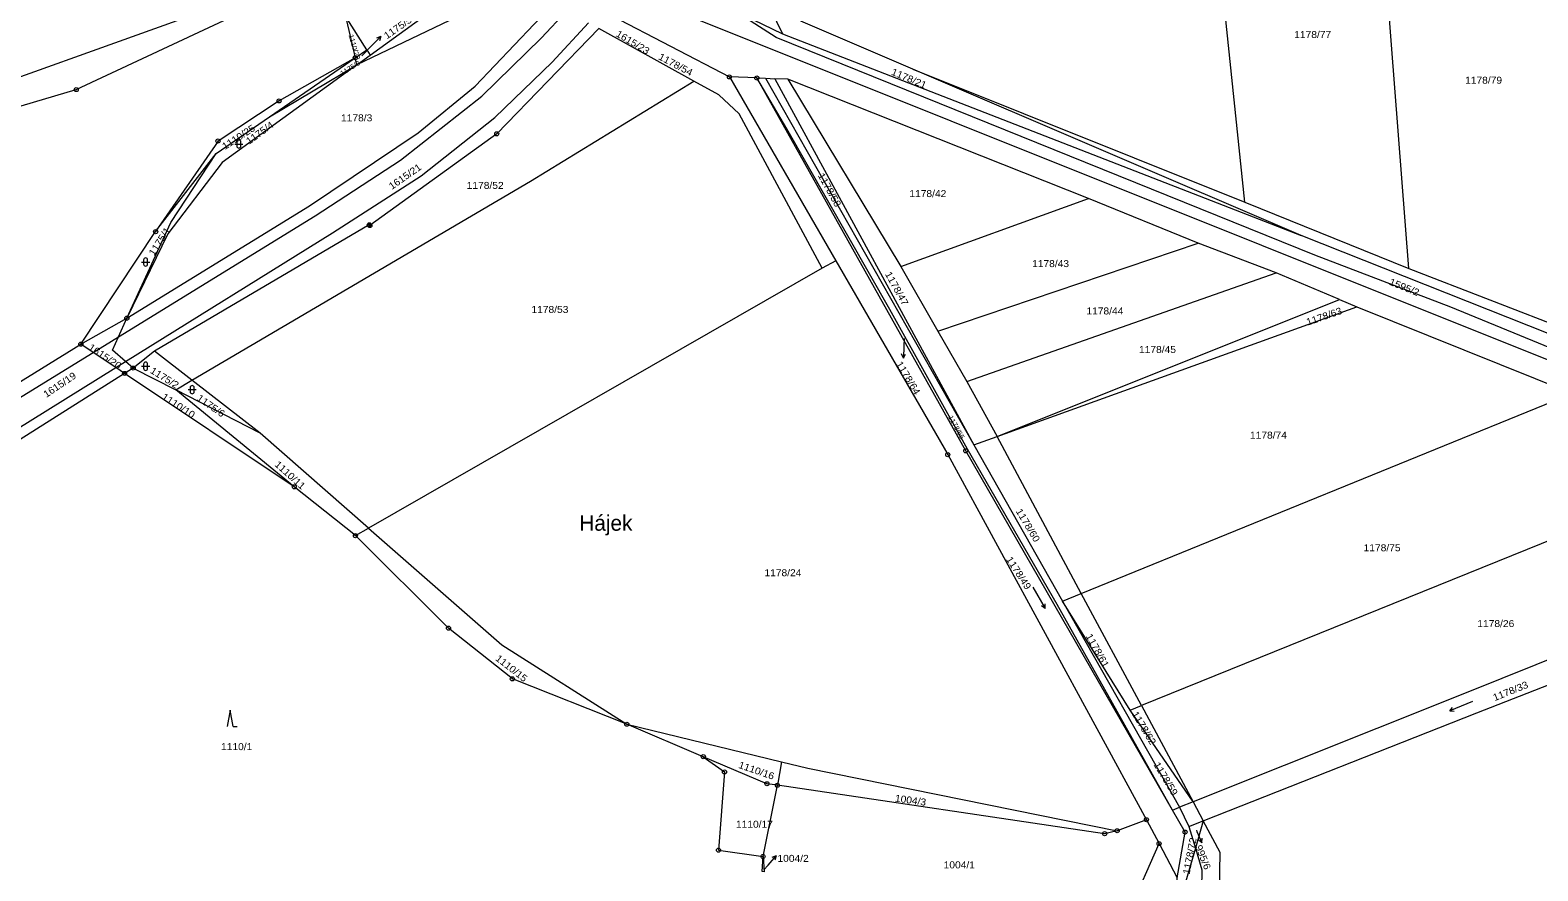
# Model space of a CAD drawing. Extents: x -686207 to -681951, y -1020493 to -1017811.
# Drawn here: x -684095.1 to -683726.8, y -1019496.1 to -1019290.6 of the extents above; entities that cross this region are included whole.
import ezdxf

# ---------------------------------------------------------------- set-up
doc = ezdxf.new("R2010")
doc.units = 0
doc.header["$LTSCALE"] = 0.4
for name, color, linetype, lineweight in [('1', 7, 'Continuous', 13), ('3', 7, 'Continuous', 13), ('4', 7, 'Continuous', 13), ('6', 7, 'Continuous', 13), ('7', 7, 'Continuous', 13), ('8', 7, 'Continuous', 13)]:
    doc.layers.add(name, color=color, linetype=linetype, lineweight=lineweight)
doc.layers.add('2', color=7, linetype='Continuous')

msp = doc.modelspace()

# ---------------------------------------------------------------- linework, layer by layer
at = {"layer": '1'}
for p, q in [((-683798.39, -1019332.66), (-683808.23, -1019238.56)), ((-683758.33, -1019348.91), (-683766.38, -1019244.39)), ((-683915.94, -1019282.08), (-683911.3, -1019291.57)), ((-684012.88, -1019295.44), (-684018.07, -1019287.22)), ((-684018.07, -1019287.22), (-684015.7, -1019297.38)), ((-683953.11, -1019287.03), (-683924.31, -1019302.07)), ((-683923.28, -1019285.78), (-683911.3, -1019291.57)), ((-683879.46, -1019300.17), (-683906.82, -1019288.43)), ((-683933.01, -1019303.08), (-683956.2, -1019290.22)), ((-683911.3, -1019291.57), (-683784.66, -1019340.83)), ((-684015.7, -1019297.38), (-684012.88, -1019295.44)), ((-684012.88, -1019295.44), (-684012.06, -1019296.74)), ((-684036.69, -1019311.81), (-684015.7, -1019297.38)), ((-684015.28, -1019299.07), (-684015.7, -1019297.38)), ((-683879.46, -1019300.17), (-683798.39, -1019332.66)), ((-683784.66, -1019340.83), (-683879.46, -1019300.17)), ((-683917.61, -1019302.32), (-683924.31, -1019302.07)), ((-683924.31, -1019302.07), (-683898.33, -1019347.01)), ((-683917.61, -1019302.32), (-683915.51, -1019302.4)), ((-683915.51, -1019302.4), (-683913.17, -1019302.49)), ((-683915.51, -1019302.4), (-683864.62, -1019391.99)), ((-683909.99, -1019302.61), (-683913.17, -1019302.49)), ((-683913.17, -1019302.49), (-683864.62, -1019391.99)), ((-684049.7, -1019320.75), (-684036.69, -1019311.81)), ((-684064.47, -1019339.88), (-684049.7, -1019320.75)), ((-683882.39, -1019348.39), (-683836.55, -1019331.79)), ((-683809.75, -1019342.71), (-683836.55, -1019331.79)), ((-683798.39, -1019332.66), (-683758.33, -1019348.91)), ((-684082.74, -1019367.38), (-684064.47, -1019339.88)), ((-683632.56, -1019401.24), (-683784.66, -1019340.83)), ((-683873.36, -1019364.19), (-683809.75, -1019342.71)), ((-683790.73, -1019349.98), (-683809.75, -1019342.71)), ((-683898.33, -1019347.01), (-683901.65, -1019348.77)), ((-683898.33, -1019347.01), (-683870.96, -1019394.37)), ((-683901.65, -1019348.77), (-684012.49, -1019412.34)), ((-683882.39, -1019348.39), (-683873.36, -1019364.19)), ((-683866.32, -1019376.52), (-683790.73, -1019349.98)), ((-683775.26, -1019356.46), (-683790.73, -1019349.98)), ((-683758.33, -1019348.91), (-683710.82, -1019367.26)), ((-683858.91, -1019389.93), (-683775.26, -1019356.46)), ((-683858.91, -1019389.93), (-683771.06, -1019358.22)), ((-683775.26, -1019356.46), (-683771.06, -1019358.22)), ((-683771.06, -1019358.22), (-683718.42, -1019379.45)), ((-683873.36, -1019364.19), (-683866.32, -1019376.52)), ((-684064.77, -1019369.08), (-684069.95, -1019373.21)), ((-684055.59, -1019376.21), (-684064.77, -1019369.08)), ((-684069.95, -1019373.21), (-684072.05, -1019374.52)), ((-684069.95, -1019373.21), (-684059.56, -1019378.55)), ((-684072.05, -1019374.52), (-684104.9, -1019395.31)), ((-684030.59, -1019402.24), (-684072.05, -1019374.52)), ((-684059.56, -1019378.55), (-684055.59, -1019376.21)), ((-684038.97, -1019389.13), (-684055.59, -1019376.21)), ((-683866.32, -1019376.52), (-683858.91, -1019389.93)), ((-684038.97, -1019389.13), (-684059.56, -1019378.55)), ((-684030.59, -1019402.24), (-684059.56, -1019378.55)), ((-684012.49, -1019412.34), (-684038.97, -1019389.13)), ((-683864.62, -1019391.99), (-683858.91, -1019389.93)), ((-683864.62, -1019391.99), (-683842.93, -1019430.16)), ((-683838.34, -1019428.29), (-683858.91, -1019389.93)), ((-683870.96, -1019394.37), (-683822.43, -1019483.6)), ((-683676.79, -1019396.24), (-683823.66, -1019455.68)), ((-684015.67, -1019414.17), (-684030.59, -1019402.24)), ((-684015.67, -1019414.17), (-684012.49, -1019412.34)), ((-683842.93, -1019430.16), (-683838.34, -1019428.29)), ((-683823.66, -1019455.68), (-683838.34, -1019428.29)), ((-683842.93, -1019430.16), (-683814.31, -1019480.54)), ((-683826.43, -1019456.8), (-683842.93, -1019430.16)), ((-683826.43, -1019456.8), (-683823.66, -1019455.68)), ((-683811.04, -1019479.23), (-683826.43, -1019456.8)), ((-683823.66, -1019455.68), (-683811.04, -1019479.23)), ((-683911.58, -1019469.44), (-683912.58, -1019475.17)), ((-683916.09, -1019492.57), (-683912.58, -1019475.17)), ((-683816.08, -1019481.24), (-683814.31, -1019480.54)), ((-683822.43, -1019483.6), (-683829.57, -1019486.29)), ((-683822.43, -1019483.6), (-683819.34, -1019489.42)), ((-683812.99, -1019486.61), (-683816.08, -1019481.24)), ((-683812.05, -1019485.28), (-683808.55, -1019483.89)), ((-683808.55, -1019483.89), (-683810.47, -1019490.52)), ((-683814.9, -1019497.76), (-683812.99, -1019486.61)), ((-683812.05, -1019485.28), (-683810.47, -1019490.52))]:
    msp.add_line(p, q, dxfattribs=at)
for points in [[(-684186.57, -1019227.46), (-684168.7, -1019292.93), (-684162.9, -1019304.17), (-684155.58, -1019310.4), (-684144.67, -1019314.55), (-684130.54, -1019316.11), (-684119.38, -1019315.7), (-684115.21, -1019314.39), (-684083.87, -1019305.16), (-684044, -1019286.52), (-684024.23, -1019277.45)], [(-684186.57, -1019227.46), (-684162.32, -1019295.76), (-684152.44, -1019306.86), (-684142.29, -1019309.68), (-684120.17, -1019310.13), (-684053.74, -1019286.29), (-684031.45, -1019278.13), (-684025.29, -1019275.77)], [(-684012.06, -1019296.74), (-683983.16, -1019275.76), (-683971.83, -1019281.7)], [(-683971.83, -1019281.7), (-683979.37, -1019281.84), (-684015.28, -1019299.07)], [(-684071.5, -1019361.03), (-684026.9, -1019333.56), (-684000.31, -1019315.71), (-683986.41, -1019304.35), (-683967.18, -1019284.14)], [(-683630.25, -1019402.31), (-683631.8, -1019405.03), (-683688.34, -1019382.86), (-683748.04, -1019358.34), (-683781.3, -1019345.59), (-683912.87, -1019292.44), (-683923.28, -1019285.78)], [(-683956.2, -1019290.22), (-683981.14, -1019315.96), (-684012.15, -1019338.39), (-684012.28, -1019338.21), (-684064.77, -1019369.08)], [(-684015.28, -1019299.07), (-684048.18, -1019322.94), (-684061.49, -1019340.44), (-684071.5, -1019361.03)], [(-684015.7, -1019297.38), (-684034.31, -1019307.93), (-684049.23, -1019317.73), (-684064.47, -1019339.88)], [(-684036.69, -1019311.81), (-684015.28, -1019299.07), (-684012.06, -1019296.74)], [(-684055.59, -1019376.21), (-683972.92, -1019327.54), (-683933.01, -1019303.08)], [(-683901.65, -1019348.77), (-683921.95, -1019311.08), (-683926.88, -1019306.48), (-683933.01, -1019303.08)], [(-683816.08, -1019481.24), (-683866.57, -1019393.43), (-683917.61, -1019302.32)], [(-683816.08, -1019481.24), (-683844.21, -1019430.98), (-683866.16, -1019393.02), (-683885.12, -1019358.9), (-683910.24, -1019314.79), (-683917.61, -1019302.32)], [(-683836.55, -1019331.79), (-683909.99, -1019302.61), (-683882.39, -1019348.39)], [(-684071.5, -1019361.03), (-684060.74, -1019337.63), (-684049.7, -1019320.75)], [(-684100.27, -1019378.22), (-684082.74, -1019367.38), (-684071.5, -1019361.03)], [(-684069.95, -1019373.21), (-684071.83, -1019371.58), (-684075.02, -1019368.82), (-684073.56, -1019365.6), (-684071.5, -1019361.03)], [(-684072.05, -1019374.52), (-684074.23, -1019373.07), (-684079.72, -1019369.4), (-684082.74, -1019367.38)], [(-683838.34, -1019428.29), (-683718.42, -1019379.45), (-683676.79, -1019396.24)], [(-683949.36, -1019460.25), (-683977.33, -1019449.17), (-683992.92, -1019436.77), (-684015.67, -1019414.17)], [(-684012.49, -1019412.34), (-683979.92, -1019440.89), (-683949.36, -1019460.25)], [(-683638.53, -1019413.06), (-683644.41, -1019417.1), (-683652.96, -1019415.84), (-683743.89, -1019452.43), (-683811.04, -1019479.23)], [(-683808.55, -1019483.89), (-683741.73, -1019457.44), (-683651.88, -1019422.36), (-683642.13, -1019423.5), (-683633.87, -1019420.2)], [(-683930.68, -1019468.19), (-683949.36, -1019460.25), (-683911.58, -1019469.44)], [(-683912.58, -1019475.17), (-683915.14, -1019474.79), (-683930.68, -1019468.19)], [(-683930.68, -1019468.19), (-683925.49, -1019471.9), (-683926.96, -1019491.03), (-683916.09, -1019492.57)], [(-683911.58, -1019469.44), (-683905.14, -1019471), (-683829.57, -1019486.29)], [(-683829.57, -1019486.29), (-683832.64, -1019487), (-683912.58, -1019475.17)], [(-683811.04, -1019479.23), (-683814.31, -1019480.54), (-683812.05, -1019485.28)], [(-683806.4, -1019604.61), (-683804.42, -1019491.59), (-683808.55, -1019483.89)], [(-683826.6, -1019505.83), (-683819.34, -1019489.42), (-683814.9, -1019497.76)], [(-683810.47, -1019490.52), (-683815.13, -1019506.57), (-683814.9, -1019497.76)], [(-683810.47, -1019490.52), (-683808.87, -1019495.84), (-683810.8, -1019603.07)]]:
    msp.add_lwpolyline(points, dxfattribs=at)
msp.add_lwpolyline([(-683915.78, -1019496.3), (-683916.26, -1019496.21), (-683916.09, -1019492.57)], close=True, dxfattribs=at)
at = {"layer": '3'}
for p, q in [((-684045.141, -1019318.461), (-684043.139, -1019318.461)), ((-684044.641, -1019317.961), (-684044.641, -1019318.962)), ((-684043.639, -1019318.962), (-684043.639, -1019317.961)), ((-684067.921, -1019347.301), (-684065.919, -1019347.301)), ((-684067.421, -1019346.801), (-684067.421, -1019347.802)), ((-684066.419, -1019347.802), (-684066.419, -1019346.801)), ((-684067.921, -1019372.771), (-684065.919, -1019372.771)), ((-684067.421, -1019372.271), (-684067.421, -1019373.272)), ((-684066.419, -1019373.272), (-684066.419, -1019372.271)), ((-684056.541, -1019378.481), (-684054.539, -1019378.481)), ((-684056.041, -1019377.981), (-684056.041, -1019378.982)), ((-684055.039, -1019378.982), (-684055.039, -1019377.981)), ((-683847.149, -1019431.937), (-683848.072, -1019431.342)), ((-683748.341, -1019456.962), (-683747.622, -1019456.131)), ((-684045.53, -1019460.84), (-684044.534, -1019460.84))]:
    msp.add_line(p, q, dxfattribs=at)
for points in [[(-683850.149, -1019426.741), (-683847.149, -1019431.937), (-683847.203, -1019430.84)], [(-683742.778, -1019454.715), (-683748.341, -1019456.962), (-683747.247, -1019457.061)], [(-684045.53, -1019460.84), (-684046.28, -1019456.84), (-684047.03, -1019460.84)]]:
    msp.add_lwpolyline(points, dxfattribs=at)
for centre, start, end in [((-684044.14, -1019317.9609), 0, 180), ((-684044.14, -1019318.9609), 180, 359.98789), ((-684066.92, -1019346.8009), 0, 180), ((-684066.92, -1019347.8009), 180, 359.98789), ((-684066.92, -1019372.2709), 0, 180), ((-684066.92, -1019373.2709), 180, 359.98789), ((-684055.54, -1019377.9809), 0, 180), ((-684055.54, -1019378.9809), 180, 359.98789)]:
    msp.add_arc(centre, 0.5, start, end, dxfattribs=at)
at = {"layer": '4'}
for p, q in [((-683967.6, -1019298.47), (-683958.75, -1019288.81)), ((-683984.8, -1019306.77), (-683970.3, -1019292.62)), ((-683981.58, -1019311.99), (-683967.6, -1019298.47)), ((-684004.67, -1019322.4), (-683984.8, -1019306.77)), ((-683999.58, -1019326.22), (-683981.58, -1019311.99)), ((-684025.51, -1019335.98), (-684004.67, -1019322.4)), ((-684021.3, -1019340.16), (-683999.58, -1019326.22)), ((-684073.56, -1019365.6), (-684025.51, -1019335.98)), ((-684071.83, -1019371.58), (-684021.3, -1019340.16)), ((-684079.72, -1019369.4), (-684073.56, -1019365.6)), ((-684101.32, -1019382.71), (-684079.72, -1019369.4)), ((-684103.9, -1019391.52), (-684074.23, -1019373.07)), ((-684074.23, -1019373.07), (-684071.83, -1019371.58)), ((-683811.04, -1019479.23), (-683808.55, -1019483.89))]:
    msp.add_line(p, q, dxfattribs=at)
msp.add_lwpolyline([(-683970.3, -1019292.62), (-683964.04, -1019285.88), (-683961.19, -1019282.81)], dxfattribs=at)
at = {"layer": '6'}
msp.add_line((-683605.51, -1019418.83), (-684039.2, -1019245.15), dxfattribs=at)
at = {"layer": '7'}
for p, q in [((-684009.438, -1019292.218), (-684010.5, -1019292.572)), ((-684014.09, -1019296.9), (-684011.56, -1019294.34)), ((-683881.64, -1019365.96), (-683881.71, -1019367.76)), ((-683881.815, -1019370.759), (-683881.279, -1019369.776)), ((-683808.859, -1019489.212), (-683808.809, -1019488.093)), ((-683912.891, -1019492.415), (-683913.926, -1019492.842))]:
    msp.add_line(p, q, dxfattribs=at)
for points in [[(-684011.56, -1019294.34), (-684009.438, -1019292.218), (-684009.792, -1019293.28)], [(-683881.71, -1019367.76), (-683881.815, -1019370.759), (-683882.28, -1019369.741)], [(-683810.22, -1019486.14), (-683810.08, -1019486.47), (-683808.859, -1019489.212), (-683809.724, -1019488.5)], [(-683915.9, -1019495.87), (-683914.86, -1019494.68), (-683912.891, -1019492.415), (-683913.17, -1019493.499)]]:
    msp.add_lwpolyline(points, dxfattribs=at)
at = {"layer": '8'}
for centre, radius in [((-684015.7, -1019297.3799), 0.5), ((-684015.7, -1019297.3799), 0.0303), ((-683924.31, -1019302.0699), 0.5), ((-683924.31, -1019302.0699), 0.0303), ((-683917.61, -1019302.3199), 0.5), ((-683917.61, -1019302.3199), 0.0303), ((-684083.87, -1019305.1599), 0.5), ((-684083.87, -1019305.1599), 0.0303), ((-684034.31, -1019307.9299), 0.5), ((-684034.31, -1019307.9299), 0.0303), ((-684049.23, -1019317.7299), 0.5), ((-684049.23, -1019317.7299), 0.0303), ((-683981.14, -1019315.9599), 0.5), ((-683981.14, -1019315.9599), 0.0303), ((-684064.47, -1019339.8799), 0.5), ((-684064.47, -1019339.8799), 0.0303), ((-684012.28, -1019338.2099), 0.5), ((-684012.15, -1019338.3899), 0.5), ((-684012.28, -1019338.2099), 0.0303), ((-684012.15, -1019338.3899), 0.0303), ((-684071.5, -1019361.0299), 0.5), ((-684071.5, -1019361.0299), 0.0303), ((-684082.74, -1019367.3799), 0.5), ((-684082.74, -1019367.3799), 0.0303), ((-684072.05, -1019374.5199), 0.5), ((-684069.95, -1019373.2099), 0.5), ((-684069.95, -1019373.2099), 0.0303), ((-684072.05, -1019374.5199), 0.0303), ((-683870.96, -1019394.3699), 0.5), ((-683870.96, -1019394.3699), 0.0303), ((-683866.57, -1019393.4299), 0.5), ((-683866.57, -1019393.4299), 0.0303), ((-684030.59, -1019402.2399), 0.5), ((-684030.59, -1019402.2399), 0.0303), ((-684015.67, -1019414.1699), 0.5), ((-684015.67, -1019414.1699), 0.0303), ((-683992.92, -1019436.7699), 0.5), ((-683992.92, -1019436.7699), 0.0303), ((-683977.33, -1019449.1699), 0.5), ((-683977.33, -1019449.1699), 0.0303), ((-683949.36, -1019460.2499), 0.5), ((-683949.36, -1019460.2499), 0.0303), ((-683930.68, -1019468.1899), 0.5), ((-683930.68, -1019468.1899), 0.0303), ((-683925.49, -1019471.8999), 0.5), ((-683925.49, -1019471.8999), 0.0303), ((-683915.14, -1019474.7899), 0.5), ((-683915.14, -1019474.7899), 0.0303), ((-683912.58, -1019475.1699), 0.5), ((-683912.58, -1019475.1699), 0.0303), ((-683822.43, -1019483.5999), 0.5), ((-683822.43, -1019483.5999), 0.0303), ((-683832.64, -1019486.9999), 0.5), ((-683832.64, -1019486.9999), 0.0303), ((-683829.57, -1019486.2899), 0.5), ((-683829.57, -1019486.2899), 0.0303), ((-683812.99, -1019486.6099), 0.5), ((-683812.99, -1019486.6099), 0.0303), ((-683926.96, -1019491.0299), 0.5), ((-683926.96, -1019491.0299), 0.0303), ((-683819.34, -1019489.4199), 0.5), ((-683819.34, -1019489.4199), 0.0303), ((-683916.09, -1019492.5699), 0.5), ((-683916.09, -1019492.5699), 0.0303)]:
    msp.add_circle(centre, radius, dxfattribs=at)

# ---------------------------------------------------------------- texts
at = {"layer": '2', "width": 1.1}
for s, height, rotation, p in [('1175/5', 1.7, 35, (-684007.962, -1019292.906)), ('1110/22', 1.19, 286, (-684017.351, -1019291.854)), ('1615/23', 1.7, 329, (-683952.217, -1019292.005)), ('1178/54', 1.7, 332, (-683941.819, -1019297.66)), ('1175/3', 1.19, 32, (-684018.924, -1019301.814)), ('1178/21', 1.7, 337, (-683884.922, -1019301.452)), ('1110/25', 1.7, 33, (-684047.557, -1019319.942)), ('1175/4', 1.7, 36, (-684041.63, -1019318.667)), ('1615/21', 1.7, 35, (-684006.762, -1019329.696)), ('1178/58', 1.7, 299, (-683902.773, -1019326.122)), ('1175/1', 1.7, 57, (-684064.887, -1019345.932)), ('1178/47', 1.7, 299, (-683886.353, -1019350.232)), ('1595/2', 1.7, 338, (-683763.288, -1019352.788)), ('1178/63', 1.7, 19, (-683783.033, -1019362.853)), ('1615/20', 1.7, 326, (-684081.065, -1019368.554)), ('1175/2', 1.7, 328, (-684065.97, -1019374.27)), ('1178/64', 1.7, 301, (-683883.668, -1019372.179)), ('1615/19', 1.7, 34, (-684091.184, -1019380.534)), ('1110/10', 1.7, 327, (-684063.142, -1019380.652)), ('1175/6', 1.7, 325, (-684054.587, -1019380.936)), ('1178/65', 1.19, 299, (-683870.89, -1019385.188)), ('1110/11', 1.7, 318, (-684035.548, -1019396.981)), ('1178/60', 1.7, 301, (-683854.428, -1019408.187)), ('1178/49', 1.7, 303, (-683856.802, -1019419.952)), ('1178/61', 1.7, 299, (-683837.313, -1019438.702)), ('1110/15', 1.7, 322, (-683981.623, -1019444.469)), ('1178/33', 1.7, 22, (-683737.371, -1019454.628)), ('1178/62', 1.7, 301, (-683826.068, -1019457.737)), ('1110/16', 1.7, 341, (-683922.236, -1019470.893)), ('1178/59', 1.7, 301, (-683820.748, -1019470.127)), ('1004/3', 1.7, 352, (-683883.948, -1019479.121)), ('1178/72', 1.7, 79, (-683811.885, -1019497.042)), ('995/6', 1.7, 292, (-683810.537, -1019490.161))]:
    msp.add_text(s, height=height, rotation=rotation, dxfattribs=at).set_placement(p)
for s, p in [('1178/77', (-683786.33, -1019292.559)), ('1178/79', (-683744.59, -1019303.72)), ('1178/3', (-684019.19, -1019312.919)), ('1178/52', (-683988.49, -1019329.419)), ('1178/42', (-683880.35, -1019331.429)), ('1178/43', (-683850.37, -1019348.539)), ('1178/53', (-683972.67, -1019359.74)), ('1178/44', (-683837.1, -1019360.11)), ('1178/45', (-683824.25, -1019369.53)), ('1178/74', (-683797.14, -1019390.46)), ('1178/75', (-683769.38, -1019417.98)), ('1178/24', (-683915.75, -1019424.08)), ('1178/26', (-683741.6, -1019436.51)), ('1110/1', (-684048.5, -1019466.58)), ('1110/17', (-683922.71, -1019485.539)), ('1004/2', (-683912.57, -1019493.883)), ('1004/1', (-683871.97, -1019495.47))]:
    msp.add_text(s, height=1.7, dxfattribs=at).set_placement(p)
at = {"layer": '7'}
msp.add_text('Hájek', height=3.8, dxfattribs=at).set_placement((-683960.98, -1019412.97))

doc.saveas('drawing.dxf')
